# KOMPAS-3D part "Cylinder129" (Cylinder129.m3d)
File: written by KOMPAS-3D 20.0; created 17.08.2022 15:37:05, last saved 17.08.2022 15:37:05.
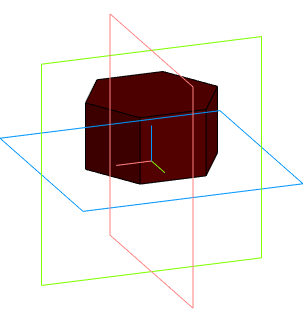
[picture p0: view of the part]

Document properties: Автор: artemsv220@gmail.com; Полное имя файла: \\192.168.2.25\новая общая папка\Медиа\Светильники\Кашпо\Кашпо и вазоны\DWG\Cylinder129.m3d

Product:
- Part/product: Cylinder129

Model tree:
1. Операция без истории:1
